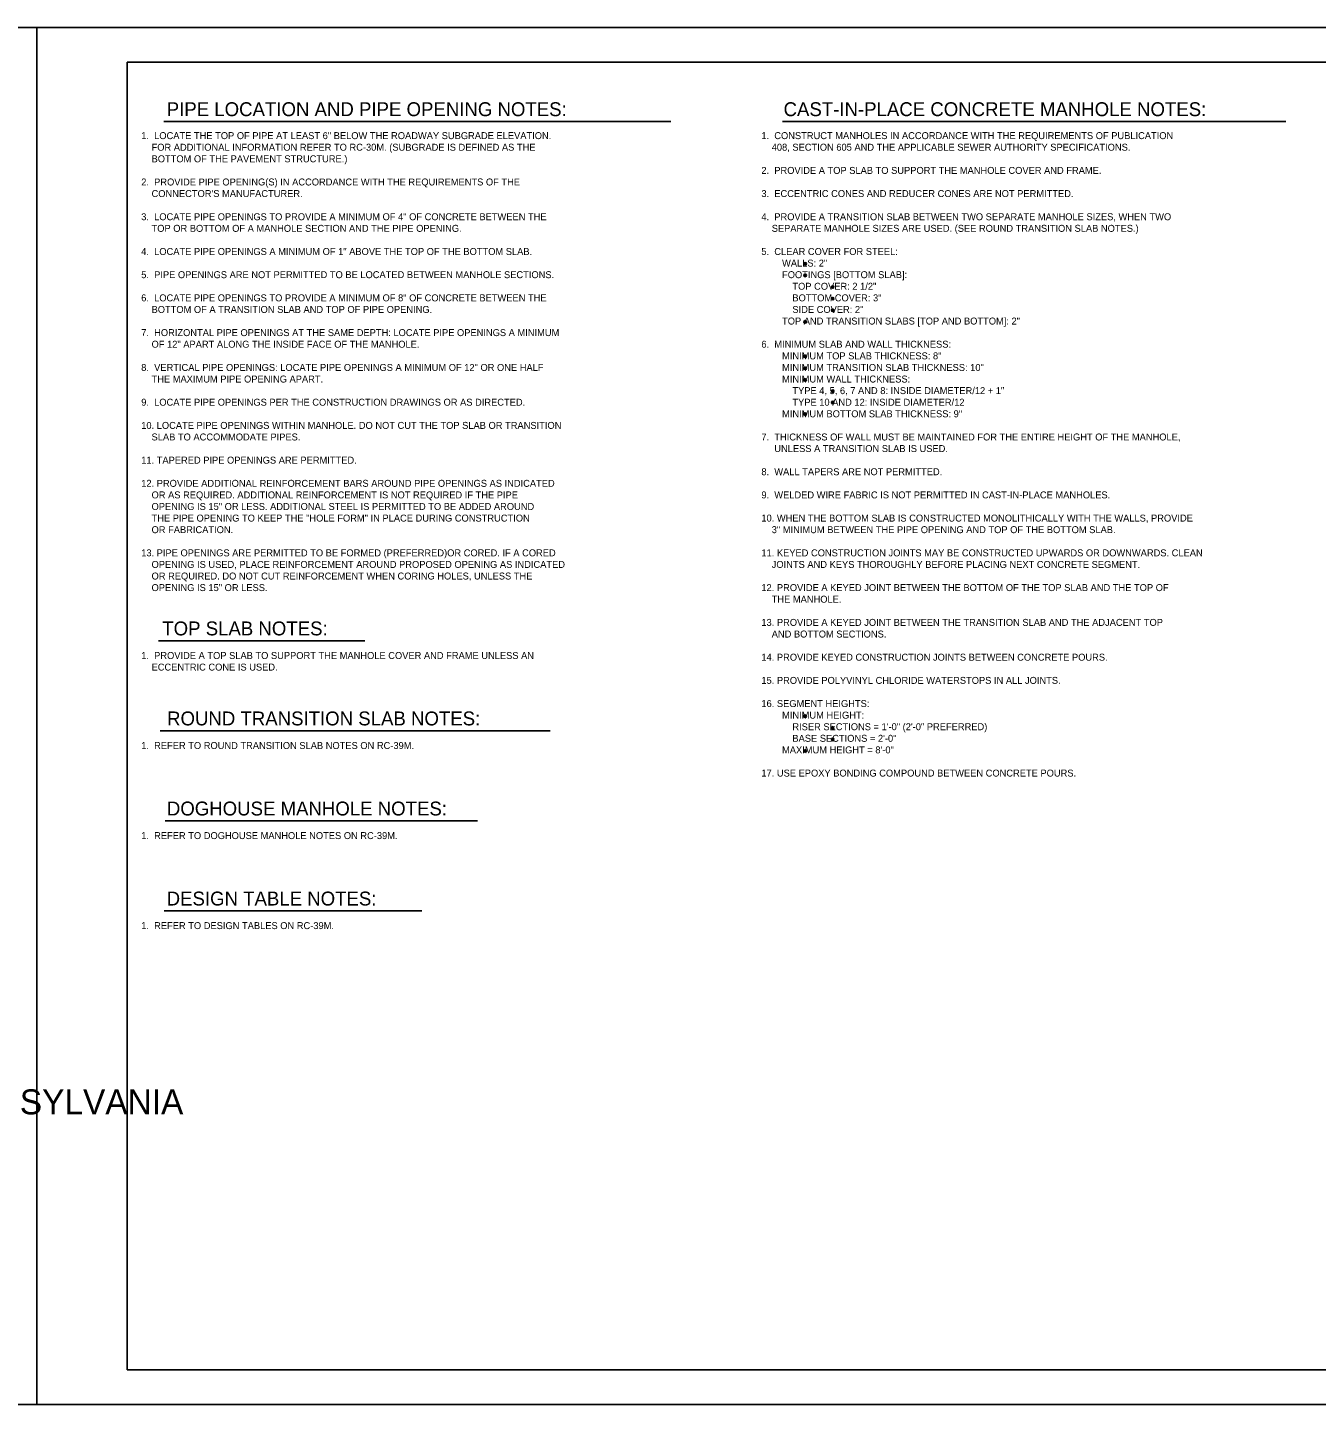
# Model space of a CAD drawing. Extents: x 2106427 to 2114911, y 988717 to 990787.
# Drawn here: x 2109172 to 2110996, y 988839 to 990787 of the extents above; entities that cross this region are included whole.
import ezdxf

# ---------------------------------------------------------------- set-up
doc = ezdxf.new("R2010")
doc.units = 0
for name, color, linetype in [('1', 7, 'Continuous'), ('3', 7, 'Continuous'), ('PLT-BNDY', 7, 'Continuous')]:
    doc.layers.add(name, color=color, linetype=linetype)

msp = doc.modelspace()

# ---------------------------------------------------------------- linework, layer by layer
at = {"layer": '1'}
for p, q in [((2109365.5, 990654.3), (2110082.6, 990654.3)), ((2110240.6, 990654.3), (2110953.3, 990654.3)), ((2109357.8, 989919.3), (2109649.9, 989919.3)), ((2109360.2, 989791.9), (2109912.2, 989791.9)), ((2109367.2, 989664.5), (2109809.3, 989664.5)), ((2109365.7, 989537.1), (2109730.2, 989537.1))]:
    msp.add_line(p, q, dxfattribs=at)
msp.add_lwpolyline([(2111892.4, 988887.7), (2111892.4, 990738.1), (2109313.6, 990738.1), (2109313.6, 988887.7), (2111892.4, 988887.7), (2111892.4, 988974.2), (2111236.2, 988974.2), (2111236.2, 989186.4), (2111892.4, 989186.4), (2111892.4, 989281.4), (2111236.2, 989281.4), (2111236.2, 988887.7), (2111494.8, 988887.7), (2111494.8, 988974.2), (2111494.8, 988887.7), (2111747.4, 988887.7), (2111747.4, 988974.2), (2111747.4, 988933.8), (2111892.4, 988933.8)], dxfattribs=at)
for centre, radius in [((2110272.9, 990453), 1.75), ((2110272.9, 990453), 1.31), ((2110272.9, 990453), 0.875), ((2110272.9, 990453), 0.437), ((2110272.9, 990436.5), 1.75), ((2110272.9, 990436.5), 1.31), ((2110272.9, 990436.5), 0.875), ((2110272.9, 990436.5), 0.437), ((2110311.9, 990420), 1.75), ((2110311.9, 990420), 1.31), ((2110311.9, 990420), 0.875), ((2110311.9, 990420), 0.437), ((2110311.9, 990403.7), 1.75), ((2110311.9, 990403.7), 1.31), ((2110311.9, 990403.7), 0.875), ((2110311.9, 990403.7), 0.437), ((2110272.9, 990370.7), 1.75), ((2110272.9, 990370.7), 1.31), ((2110272.9, 990370.7), 0.875), ((2110272.9, 990370.7), 0.437), ((2110311.9, 990387.1), 1.75), ((2110311.9, 990387.1), 1.31), ((2110311.9, 990387.1), 0.875), ((2110311.9, 990387.1), 0.437), ((2110272.9, 990321.9), 1.75), ((2110272.9, 990321.9), 1.31), ((2110272.9, 990321.9), 0.875), ((2110272.9, 990321.9), 0.437), ((2110272.9, 990304.9), 1.75), ((2110272.9, 990304.9), 1.31), ((2110272.9, 990304.9), 0.875), ((2110272.9, 990304.9), 0.437), ((2110272.9, 990288.5), 1.75), ((2110272.9, 990288.5), 1.31), ((2110272.9, 990288.5), 0.875), ((2110272.9, 990288.5), 0.437), ((2110311.9, 990272.7), 1.75), ((2110311.9, 990272.7), 1.31), ((2110311.9, 990272.7), 0.875), ((2110311.9, 990272.7), 0.437), ((2110311.9, 990256.6), 1.75), ((2110311.9, 990256.6), 1.31), ((2110311.9, 990256.6), 0.875), ((2110311.9, 990256.6), 0.437), ((2110272.9, 990240.2), 1.75), ((2110272.9, 990240.2), 1.31), ((2110272.9, 990240.2), 0.875), ((2110272.9, 990240.2), 0.437), ((2110272.9, 989812.6), 1.75), ((2110272.9, 989812.6), 1.31), ((2110272.9, 989812.6), 0.875), ((2110272.9, 989812.6), 0.437), ((2110311.9, 989796.1), 1.75), ((2110311.9, 989796.1), 1.31), ((2110311.9, 989796.1), 0.875), ((2110311.9, 989796.1), 0.437), ((2110311.9, 989779.7), 1.75), ((2110311.9, 989779.7), 1.31), ((2110311.9, 989779.7), 0.875), ((2110311.9, 989779.7), 0.437), ((2110272.9, 989763.5), 1.75), ((2110272.9, 989763.5), 1.31), ((2110272.9, 989763.5), 0.875), ((2110272.9, 989763.5), 0.437)]:
    msp.add_circle(centre, radius, dxfattribs=at)
at = {"layer": 'PLT-BNDY'}
for points in [[(2106426.5, 990787.3), (2109185.7, 990787.3), (2109185.7, 988838.5), (2106426.5, 988838.5)], [(2109185.7, 990787.3), (2111944.9, 990787.3), (2111944.9, 988838.5), (2109185.7, 988838.5)]]:
    msp.add_lwpolyline(points, close=True, dxfattribs=at)

# ---------------------------------------------------------------- texts
at = {"layer": '3'}
for s, height, p in [('PIPE LOCATION AND PIPE OPENING NOTES:', 19.685, (2109369.4, 990661.9)), ('CAST-IN-PLACE CONCRETE MANHOLE NOTES:', 19.685, (2110242.3, 990661.9)), ('1.  LOCATE THE TOP OF PIPE AT LEAST 6" BELOW THE ROADWAY SUBGRADE ELEVATION.', 9.843, (2109333.3, 990629.4)), ('1.  CONSTRUCT MANHOLES IN ACCORDANCE WITH THE REQUIREMENTS OF PUBLICATION', 9.843, (2110210.9, 990629.4)), ('    FOR ADDITIONAL INFORMATION REFER TO RC-30M. (SUBGRADE IS DEFINED AS THE', 9.843, (2109333.3, 990613)), ('    BOTTOM OF THE PAVEMENT STRUCTURE.)', 9.843, (2109333.3, 990596.6)), ('    408, SECTION 605 AND THE APPLICABLE SEWER AUTHORITY SPECIFICATIONS.', 9.843, (2110210.9, 990613)), ('2.  PROVIDE A TOP SLAB TO SUPPORT THE MANHOLE COVER AND FRAME.', 9.843, (2110210.9, 990580.2)), ('2.  PROVIDE PIPE OPENING(S) IN ACCORDANCE WITH THE REQUIREMENTS OF THE', 9.843, (2109333.3, 990563.8)), ("    CONNECTOR'S MANUFACTURER.", 9.843, (2109333.3, 990547.4)), ('3.  ECCENTRIC CONES AND REDUCER CONES ARE NOT PERMITTED.', 9.843, (2110210.9, 990547.4)), ('3.  LOCATE PIPE OPENINGS TO PROVIDE A MINIMUM OF 4" OF CONCRETE BETWEEN THE', 9.843, (2109333.3, 990514.6)), ('    TOP OR BOTTOM OF A MANHOLE SECTION AND THE PIPE OPENING.', 9.843, (2109333.3, 990498.2)), ('4.  PROVIDE A TRANSITION SLAB BETWEEN TWO SEPARATE MANHOLE SIZES, WHEN TWO', 9.843, (2110210.9, 990514.6)), ('    SEPARATE MANHOLE SIZES ARE USED. (SEE ROUND TRANSITION SLAB NOTES.)', 9.843, (2110210.9, 990498.2)), ('4.  LOCATE PIPE OPENINGS A MINIMUM OF 1" ABOVE THE TOP OF THE BOTTOM SLAB.', 9.843, (2109333.3, 990465.4)), ('5.  CLEAR COVER FOR STEEL:', 9.843, (2110210.9, 990465.4)), ('        WALLS: 2" ', 9.843, (2110210.9, 990449)), ('5.  PIPE OPENINGS ARE NOT PERMITTED TO BE LOCATED BETWEEN MANHOLE SECTIONS.', 9.843, (2109333.3, 990432.6)), ('        FOOTINGS [BOTTOM SLAB]:', 9.843, (2110210.9, 990432.6)), ('6.  LOCATE PIPE OPENINGS TO PROVIDE A MINIMUM OF 8" OF CONCRETE BETWEEN THE', 9.843, (2109333.3, 990399.8)), ('            TOP COVER: 2 1/2"', 9.843, (2110210.9, 990416.2)), ('            BOTTOM COVER: 3"', 9.843, (2110210.9, 990399.8)), ('    BOTTOM OF A TRANSITION SLAB AND TOP OF PIPE OPENING.', 9.843, (2109333.3, 990383.4)), ('            SIDE COVER: 2"', 9.843, (2110210.9, 990383.4)), ('        TOP AND TRANSITION SLABS [TOP AND BOTTOM]: 2"', 9.843, (2110210.9, 990367)), ('7.  HORIZONTAL PIPE OPENINGS AT THE SAME DEPTH: LOCATE PIPE OPENINGS A MINIMUM', 9.843, (2109333.3, 990350.6)), ('    OF 12" APART ALONG THE INSIDE FACE OF THE MANHOLE.', 9.843, (2109333.3, 990334.2)), ('6.  MINIMUM SLAB AND WALL THICKNESS:', 9.843, (2110210.9, 990334.2)), ('        MINIMUM TOP SLAB THICKNESS: 8"', 9.843, (2110210.9, 990317.7)), ('8.  VERTICAL PIPE OPENINGS: LOCATE PIPE OPENINGS A MINIMUM OF 12" OR ONE HALF', 9.843, (2109333.3, 990301.3)), ('    THE MAXIMUM PIPE OPENING APART.', 9.843, (2109333.3, 990284.9)), ('        MINIMUM TRANSITION SLAB THICKNESS: 10"', 9.843, (2110210.9, 990301.3)), ('        MINIMUM WALL THICKNESS:', 9.843, (2110210.9, 990284.9)), ('            TYPE 4, 5, 6, 7 AND 8: INSIDE DIAMETER/12 + 1"', 9.843, (2110210.9, 990268.5)), ('9.  LOCATE PIPE OPENINGS PER THE CONSTRUCTION DRAWINGS OR AS DIRECTED.', 9.843, (2109333.3, 990252.1)), ('            TYPE 10 AND 12: INSIDE DIAMETER/12            ', 9.843, (2110210.9, 990252.1)), ('        MINIMUM BOTTOM SLAB THICKNESS: 9"', 9.843, (2110210.9, 990235.7)), ('10. LOCATE PIPE OPENINGS WITHIN MANHOLE. DO NOT CUT THE TOP SLAB OR TRANSITION', 9.843, (2109333.3, 990219.3)), ('    SLAB TO ACCOMMODATE PIPES.', 9.843, (2109333.3, 990202.9)), ('7.  THICKNESS OF WALL MUST BE MAINTAINED FOR THE ENTIRE HEIGHT OF THE MANHOLE,', 9.843, (2110210.9, 990202.9)), ('     UNLESS A TRANSITION SLAB IS USED.', 9.843, (2110210.9, 990186.5)), ('11. TAPERED PIPE OPENINGS ARE PERMITTED.', 9.843, (2109333.3, 990170.1)), ('8.  WALL TAPERS ARE NOT PERMITTED.', 9.843, (2110210.9, 990153.7)), ('12. PROVIDE ADDITIONAL REINFORCEMENT BARS AROUND PIPE OPENINGS AS INDICATED', 9.843, (2109333.3, 990137.3)), ('    OR AS REQUIRED. ADDITIONAL REINFORCEMENT IS NOT REQUIRED IF THE PIPE', 9.843, (2109333.3, 990120.9)), ('9.  WELDED WIRE FABRIC IS NOT PERMITTED IN CAST-IN-PLACE MANHOLES.', 9.843, (2110210.9, 990120.9)), ('    THE PIPE OPENING TO KEEP THE "HOLE FORM" IN PLACE DURING CONSTRUCTION', 9.843, (2109333.3, 990088.1)), ('    OPENING IS 15" OR LESS. ADDITIONAL STEEL IS PERMITTED TO BE ADDED AROUND', 9.843, (2109333.3, 990104.5)), ('10. WHEN THE BOTTOM SLAB IS CONSTRUCTED MONOLITHICALLY WITH THE WALLS, PROVIDE', 9.843, (2110210.9, 990088.1)), ('    OR FABRICATION.', 9.843, (2109333.3, 990071.7)), ('    3" MINIMUM BETWEEN THE PIPE OPENING AND TOP OF THE BOTTOM SLAB.', 9.843, (2110210.9, 990071.7)), ('13. PIPE OPENINGS ARE PERMITTED TO BE FORMED (PREFERRED)OR CORED. IF A CORED', 9.843, (2109333.3, 990038.9)), ('11. KEYED CONSTRUCTION JOINTS MAY BE CONSTRUCTED UPWARDS OR DOWNWARDS. CLEAN', 9.843, (2110210.9, 990038.9)), ('    OPENING IS USED, PLACE REINFORCEMENT AROUND PROPOSED OPENING AS INDICATED', 9.843, (2109333.3, 990022.5)), ('    JOINTS AND KEYS THOROUGHLY BEFORE PLACING NEXT CONCRETE SEGMENT.', 9.843, (2110210.9, 990022.5)), ('    OR REQUIRED. DO NOT CUT REINFORCEMENT WHEN CORING HOLES, UNLESS THE', 9.843, (2109333.3, 990006.1)), ('    OPENING IS 15" OR LESS.', 9.843, (2109333.3, 989989.7)), ('12. PROVIDE A KEYED JOINT BETWEEN THE BOTTOM OF THE TOP SLAB AND THE TOP OF', 9.843, (2110210.9, 989989.7)), ('    THE MANHOLE.', 9.843, (2110210.9, 989973.3)), ('TOP SLAB NOTES:', 19.685, (2109363.1, 989927)), ('13. PROVIDE A KEYED JOINT BETWEEN THE TRANSITION SLAB AND THE ADJACENT TOP', 9.843, (2110210.9, 989940.5)), ('    AND BOTTOM SECTIONS.', 9.843, (2110210.9, 989924)), ('1.  PROVIDE A TOP SLAB TO SUPPORT THE MANHOLE COVER AND FRAME UNLESS AN', 9.843, (2109333.3, 989893.6)), ('    ECCENTRIC CONE IS USED.', 9.843, (2109333.3, 989877.2)), ('14. PROVIDE KEYED CONSTRUCTION JOINTS BETWEEN CONCRETE POURS.', 9.843, (2110210.9, 989891.2)), ('15. PROVIDE POLYVINYL CHLORIDE WATERSTOPS IN ALL JOINTS.', 9.843, (2110210.9, 989858.4)), ('16. SEGMENT HEIGHTS:', 9.843, (2110210.9, 989825.6)), ('ROUND TRANSITION SLAB NOTES:', 19.685, (2109369.9, 989799.6)), ('        MINIMUM HEIGHT:', 9.843, (2110210.9, 989809.2)), ('            RISER SECTIONS = 1\'-0" (2\'-0" PREFERRED)', 9.843, (2110210.9, 989792.8)), ('            BASE SECTIONS = 2\'-0"', 9.843, (2110210.9, 989776.4)), ('1.  REFER TO ROUND TRANSITION SLAB NOTES ON RC-39M.', 9.843, (2109333.3, 989766.2)), ('        MAXIMUM HEIGHT = 8\'-0"', 9.843, (2110210.9, 989760)), ('17. USE EPOXY BONDING COMPOUND BETWEEN CONCRETE POURS.', 9.843, (2110210.9, 989727.2)), ('DOGHOUSE MANHOLE NOTES:', 19.685, (2109369.6, 989672.1)), ('1.  REFER TO DOGHOUSE MANHOLE NOTES ON RC-39M.', 9.843, (2109333.3, 989638.7)), ('DESIGN TABLE NOTES:', 19.685, (2109369.3, 989544.7)), ('1.  REFER TO DESIGN TABLES ON RC-39M.', 9.843, (2109333.3, 989511.3)), ('COMMONWEALTH OF PENNSYLVANIA', 35.379, (2108520.2, 989249.1))]:
    msp.add_text(s, height=height, dxfattribs=at).set_placement(p)

doc.saveas('drawing.dxf')
